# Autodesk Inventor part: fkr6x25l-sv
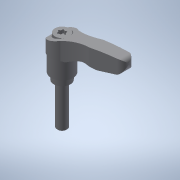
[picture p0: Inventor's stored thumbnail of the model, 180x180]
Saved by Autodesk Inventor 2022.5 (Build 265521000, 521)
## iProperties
Created: 2017-09
Part Number: fkr6x25l-sv
Material: 一般
Document SubType Name: Modeling
Designer: imaocorp
Density: 1 g/cm^3
Appearance: 既定
Author: imaocorp
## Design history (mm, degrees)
node "fkr6x25l-sv.x_t1"
node "fkr6x25l-sv"
node "Base1"
